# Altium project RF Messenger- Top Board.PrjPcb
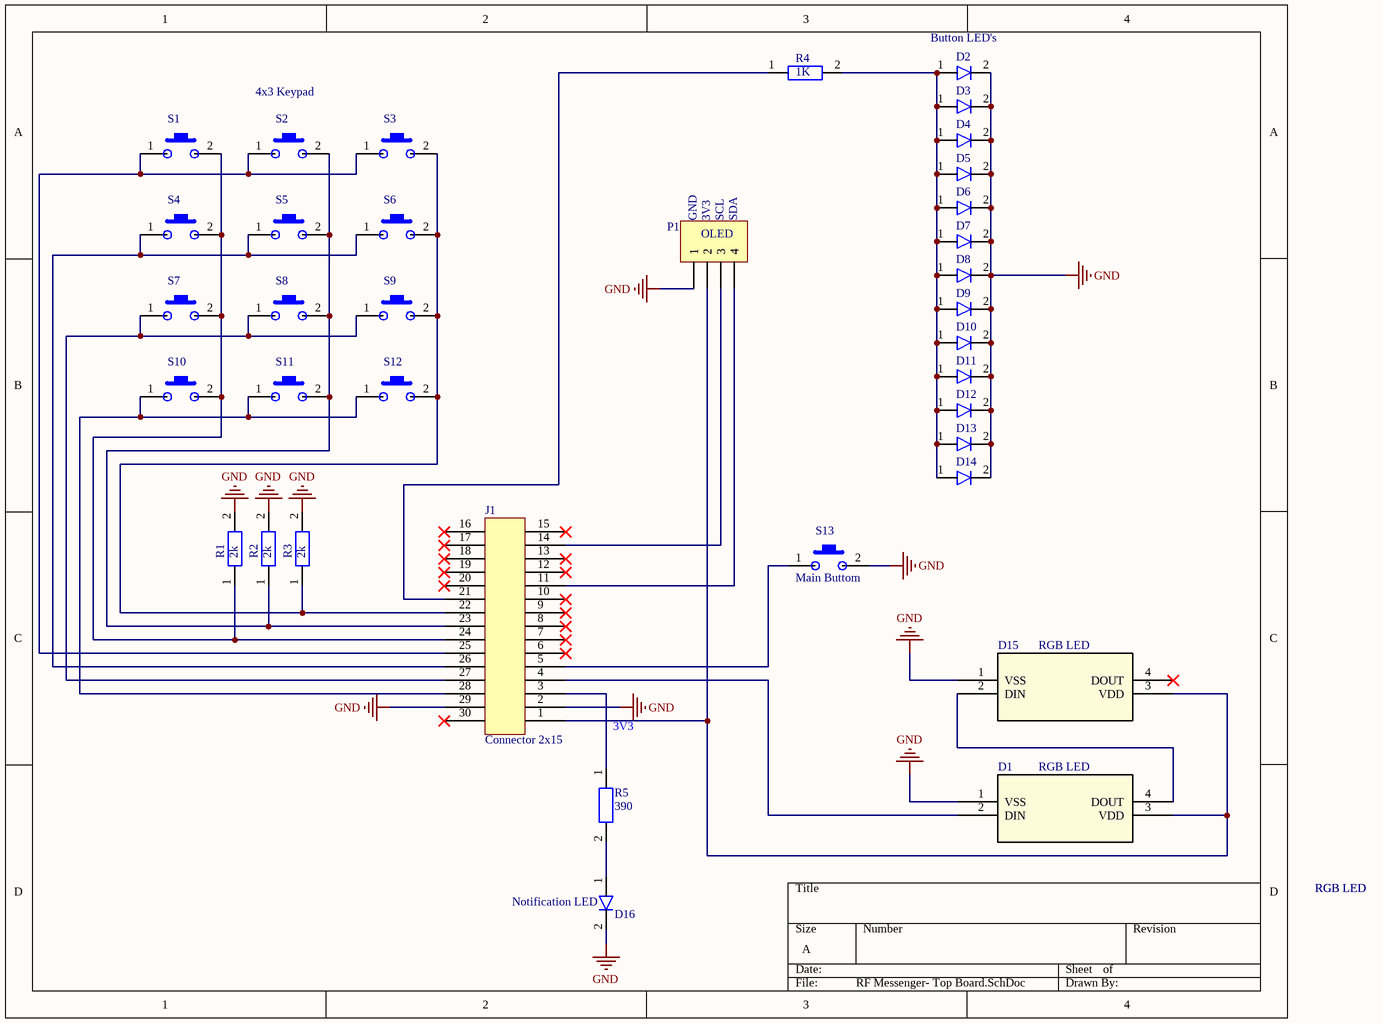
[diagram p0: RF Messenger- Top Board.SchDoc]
1 sheet, 36 parts. Net scope: global (net labels, ports and power ports of the same name join across sheets).
Board file: RF Messenger- Top Board.PcbDoc

## Sheet RF Messenger- Top Board.SchDoc: RF Messenger- Top Board
size A; Author: Angel Cruz; DrawnBy: Angel Cruz

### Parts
D1  1655  [LED_1655_ADA]  (value not drawn)
D2  LED 2  [XZDGK45WT-9]  (value not drawn)
D3  LED 2  [XZDGK45WT-9]  (value not drawn)
D4  LED 2  [XZDGK45WT-9]  (value not drawn)
D5  LED 2  [XZDGK45WT-9]  (value not drawn)
D6  LED 2  [XZDGK45WT-9]  (value not drawn)
D7  LED 2  [XZDGK45WT-9]  (value not drawn)
D8  LED 2  [XZDGK45WT-9]  (value not drawn)
D9  LED 2  [XZDGK45WT-9]  (value not drawn)
D10  LED 2  [XZDGK45WT-9]  (value not drawn)
D11  LED 2  [XZDGK45WT-9]  (value not drawn)
D12  LED 2  [XZDGK45WT-9]  (value not drawn)
D13  LED 2  [XZDGK45WT-9]  (value not drawn)
D14  LED 2  [XZDGK45WT-9]  (value not drawn)
D15  1655  [LED_1655_ADA]  (value not drawn)
D16  LED 2  [XZDGK45WT-9]  (value not drawn)
J1  Connector 2x15  [RF Messenger Connector Headers - duplicate]
P1  Header 4  [OLED]  (value not drawn)
R1  2k  [Resistor 1812_PAN-M]
R2  2k  [Resistor 1812_PAN-M]
R3  2k  [Resistor 1812_PAN-M]
R4  1K  [Resistor 1812_PAN-M]
R5  390  [Resistor 1812_PAN-M]
S1  Switch  [Tactile Switch (PTS636 SP50 LFS) THT]  (value not drawn)
S2  Switch  [Tactile Switch (PTS636 SP50 LFS) THT]  (value not drawn)
S3  Switch  [Tactile Switch (PTS636 SP50 LFS) THT]  (value not drawn)
S4  Switch  [Tactile Switch (PTS636 SP50 LFS) THT]  (value not drawn)
S5  Switch  [Tactile Switch (PTS636 SP50 LFS) THT]  (value not drawn)
S6  Switch  [Tactile Switch (PTS636 SP50 LFS) THT]  (value not drawn)
S7  Switch  [Tactile Switch (PTS636 SP50 LFS) THT]  (value not drawn)
S8  Switch  [Tactile Switch (PTS636 SP50 LFS) THT]  (value not drawn)
S9  Switch  [Tactile Switch (PTS636 SP50 LFS) THT]  (value not drawn)
S10  Switch  [Tactile Switch (PTS636 SP50 LFS) THT]  (value not drawn)
S11  Switch  [Tactile Switch (PTS636 SP50 LFS) THT]  (value not drawn)
S12  Switch  [Tactile Switch (PTS636 SP50 LFS) THT]  (value not drawn)
S13  Switch  [Tactile Switch (PTS636 SP50 LFS) THT]  (value not drawn)

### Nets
GND: D1.1(VSS) D2.2 D3.2 D4.2 D5.2 D6.2 D7.2 D8.2 D9.2 D10.2 D11.2 D12.2 D13.2 D14.2 D15.1(VSS) D16.2 J1.2 J1.29 P1.1 R1.2 R2.2 R3.2 S13.2
NetD1_2: D1.2(DIN) J1.4
NetD1_3: D1.3(VDD) D15.3(VDD) J1.1 P1.2
NetD1_4: D1.4(DOUT) D15.2(DIN)
NetD2_1: D2.1 D3.1 D4.1 D5.1 D6.1 D7.1 D8.1 D9.1 D10.1 D11.1 D12.1 D13.1 D14.1 R4.2
NetD16_1: D16.1 R5.2
NetJ1_3: J1.3 R5.1
NetJ1_5: J1.5 S13.1
NetJ1_11: J1.11 P1.4
NetJ1_14: J1.14 P1.3
NetJ1_21: J1.21 R4.1
NetJ1_22: J1.22 R3.1 S3.2 S6.2 S9.2 S12.2
NetJ1_23: J1.23 R2.1 S2.2 S5.2 S8.2 S11.2
NetJ1_24: J1.24 R1.1 S1.2 S4.2 S7.2 S10.2
NetJ1_25: J1.25 S1.1 S2.1 S3.1
NetJ1_26: J1.26 S4.1 S5.1 S6.1
NetJ1_27: J1.27 S7.1 S8.1 S9.1
NetJ1_28: J1.28 S10.1 S11.1 S12.1

Not connected (* = marked no-connect by the designer): D15 4(DOUT)*; J1 6* 7* 8* 9* 10* 12* 13* 15* 16* 17* 18* 19* 20* 30*

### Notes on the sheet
- 4x3 Keypad
- (near D2) Button LED's
- (near P1) GND
- (near P1) OLED
- (near P1) 3V3
- (near P1) SCL
- (near P1) SDA
- (near S13) Main Buttom
- (near D15) RGB LED
- 3V3
- (near D1) RGB LED
- (near D16) Notification LED
- RGB LED

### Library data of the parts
D1 D15 = 1655 Neopixel: Adafruit 1655 Neopixel 5.00mm L x 5.00mm W (footprint downloaded); Built_By: EMA_Colton; Vendor: Adafruit Industries; SourceLibrary: Adafruit_2019-12-18; Type: DEV
D2-D14 D16 = LED 2: Generic LED
J1 = Connector 2x15: 15 Pin Connector
P1 = Header 4: Header, 4-Pin
R1-R3 = Resistor SMD 1206: SMD Resistor 1206 (3216 Metric)
R4 R5 = Resistor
